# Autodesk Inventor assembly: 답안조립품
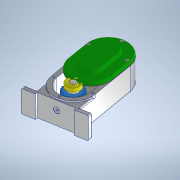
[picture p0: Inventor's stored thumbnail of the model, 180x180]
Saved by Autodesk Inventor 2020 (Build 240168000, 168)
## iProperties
Created: 2021-05
Part Number: 답안조립품
Document SubType Name: Assembly
Designer: OWner
Author: OWner
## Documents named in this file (17)
- C:\Users\OWner\Desktop\710507V1017\답안조립품.iam
- C:\Users\OWner\Desktop\710507V1017\답안도면.ipt
- C:\Users\OWner\Desktop\710507V1017\베어링 6001.ipt
- 베어링 6001.ipt
- C:\Users\OWner\Desktop\710507V1017\커버 B.ipt
- C:\Users\OWner\Desktop\710507V1017\볼트 M4.ipt
- C:\Users\OWner\Desktop\710507V1017\축 A.ipt
- C:\Users\OWner\Desktop\710507V1017\칼라.ipt
- C:\Users\OWner\Desktop\710507V1017\키 5 x 5 x 12.ipt
- C:\Users\OWner\Desktop\710507V1017\스퍼기어 A.ipt
- C:\Users\OWner\Desktop\710507V1017\베어링 6002.ipt
- 베어링 6002.ipt
- C:\Users\OWner\Desktop\710507V1017\축 B.ipt
- C:\Users\OWner\Desktop\710507V1017\키 4 x 4 x 12.ipt
- C:\Users\OWner\Desktop\710507V1017\스퍼기어 B.ipt
- C:\Users\OWner\Desktop\710507V1017\개스킷 A.ipt
- C:\Users\OWner\Desktop\710507V1017\커버 A.ipt
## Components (1 placed, 1 different names)
1. 개스킷 A:1
